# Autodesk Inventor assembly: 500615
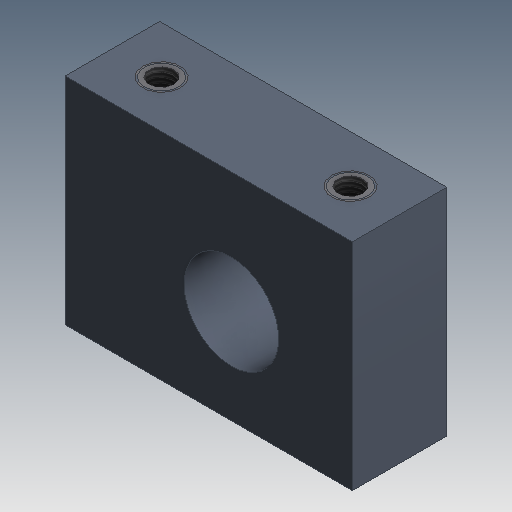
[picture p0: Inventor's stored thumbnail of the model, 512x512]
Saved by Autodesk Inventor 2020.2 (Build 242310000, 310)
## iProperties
Created: 2000-02
Part Number: 500615
Document SubType Name: Assembly
Description: PLT-03,SN,EX,10,030,023,XXX,CYLINDER MOUNT BLOCK
Designer: sspink
Mass: 112.544 g
Surface Area: 187.413 cm^2
Volume: 93.9218 cm^3
Density: 1.19828 g/cm^3
Control State: 0
Checked Out: False
Master: False
Shininess: 0.0
Length Units: 11272
Angle Units: 11279
Time Units: 11290
Mass Units: 11286
Length Display Precision: 3
Angle Display Precision: 2
Compacted: True
Dimensions: 2,2x1x3 in
Mass: 0,248 lb
DocNumber: 500615.iam
Folder: 01 - Themengebiete\Simplification\01 - Packaging machine\
VDS_Category: 3D Komponenten
Density: 0.0
Volumn: 0.0
Area: 0.0
PropertySet Name: Model Information
Author: sspink
Revision Number: -
Title: PLT-03,SN,EX,10,030,023,XXX,CYLINDER MOUNT BLOCK
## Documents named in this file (3)
- D:\07 - DEMODATEN\OTX 2019 - Dataset - UPDATE - Dez2019\Designs\07-Packing machine\500615.iam
- D:\07 - DEMODATEN\OTX 2019 - Dataset - UPDATE - Dez2019\Designs\07-Packing machine\Parts\ADSK-011572.ipt
- D:\07 - DEMODATEN\OTX 2019 - Dataset - UPDATE - Dez2019\Designs\07-Packing machine\Parts\ADSK-011736.ipt
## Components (3 placed, 2 different names)
1. ADSK-011572:1 — Insert:1, Insert:2
2. ADSK-011736:1 — Insert:1
3. ADSK-011736:2 — Insert:2
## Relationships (2: Insert 2)
- Insert:1: ADSK-011572:1 ↔ ADSK-011736:1
- Insert:2: ADSK-011572:1 ↔ ADSK-011736:2
